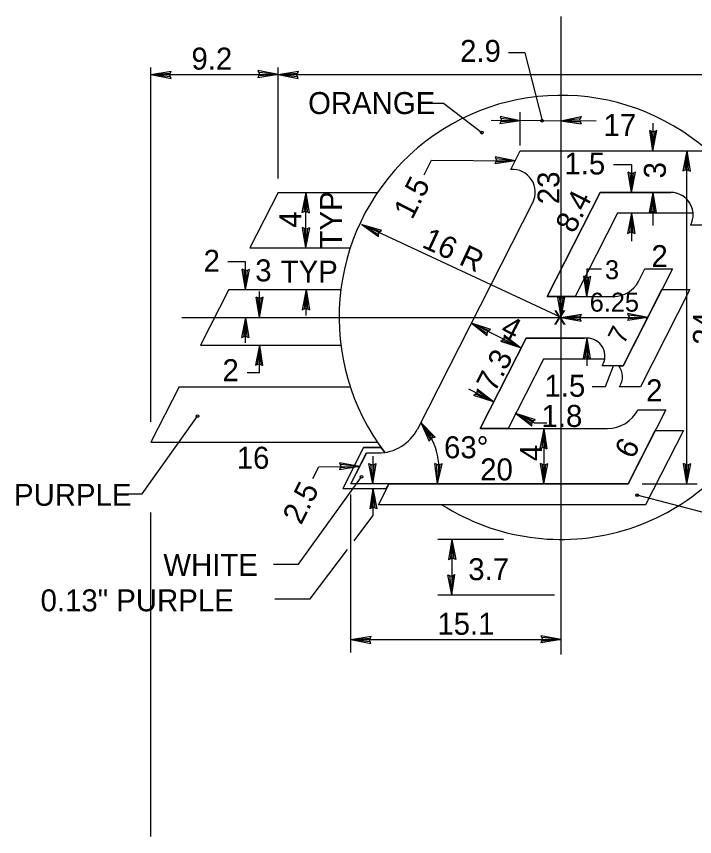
# Model space of a CAD drawing. Extents: x 10268197 to 10268739, y 2141503 to 2142677.
# Drawn here: x 10268594.88 to 10268620.18, y 2142394.49 to 2142425.07 of the extents above; entities that cross this region are included whole.
import ezdxf

# ---------------------------------------------------------------- set-up
doc = ezdxf.new("R2010")
doc.units = 0
doc.layers.add('1', color=7, linetype='Continuous')
doc.layers.add('Default', color=7, linetype='Continuous')

msp = doc.modelspace()

# ---------------------------------------------------------------- linework, layer by layer
at = {"layer": '1'}
for p, q in [((10268615.194, 2142401.275), (10268615.194, 2142425.067)), ((10268613.842, 2142423.705), (10268613.233, 2142423.709)), ((10268613.842, 2142423.705), (10268614.486, 2142421.186)), ((10268599.897, 2142409.949), (10268599.897, 2142423.161)), ((10268604.638, 2142419.022), (10268604.638, 2142423.161)), ((10268599.897, 2142422.903), (10268627.032, 2142422.903)), ((10268609.875, 2142421.837), (10268610.811, 2142421.837)), ((10268610.811, 2142421.837), (10268612.239, 2142420.735)), ((10268613.674, 2142420.255), (10268613.674, 2142421.491)), ((10268616.504, 2142421.161), (10268612.583, 2142421.189)), ((10268618.623, 2142421.091), (10268618.623, 2142420.056)), ((10268619.885, 2142407.638), (10268619.885, 2142420.056)), ((10268610.085, 2142419.159), (10268610.366, 2142419.708)), ((10268610.366, 2142419.708), (10268613.483, 2142419.68)), ((10268617.823, 2142419.539), (10268617.147, 2142419.539)), ((10268617.823, 2142419.539), (10268617.823, 2142418.504)), ((10268605.673, 2142416.434), (10268605.673, 2142418.504)), ((10268614.678, 2142414.624), (10268616.655, 2142418.504)), ((10268616.655, 2142418.504), (10268619.293, 2142418.504)), ((10268618.623, 2142418.504), (10268618.623, 2142417.274)), ((10268617.305, 2142417.728), (10268615.723, 2142414.624)), ((10268620.12, 2142417.728), (10268617.305, 2142417.728)), ((10268617.823, 2142417.728), (10268617.823, 2142416.693)), ((10268615.194, 2142413.847), (10268607.764, 2142417.312)), ((10268603.421, 2142415.917), (10268602.766, 2142415.921)), ((10268603.421, 2142414.882), (10268603.421, 2142415.917)), ((10268616.158, 2142415.659), (10268616.158, 2142414.624)), ((10268616.158, 2142415.659), (10268616.708, 2142415.659)), ((10268605.685, 2142413.912), (10268605.685, 2142414.882)), ((10268617.505, 2142412.037), (10268618.955, 2142414.882)), ((10268620, 2142414.882), (10268618.154, 2142411.26)), ((10268618.955, 2142414.882), (10268620, 2142414.882)), ((10268603.939, 2142413.847), (10268603.939, 2142414.812)), ((10268615.723, 2142414.624), (10268614.678, 2142414.624)), ((10268601.046, 2142413.847), (10268618.427, 2142413.847)), ((10268603.421, 2142412.902), (10268603.421, 2142413.847)), ((10268613.681, 2142412.706), (10268611.836, 2142413.646)), ((10268612.174, 2142409.708), (10268613.888, 2142413.071)), ((10268613.888, 2142413.071), (10268616.061, 2142413.064)), ((10268616.158, 2142413.071), (10268616.158, 2142412.037)), ((10268603.939, 2142411.778), (10268603.939, 2142412.812)), ((10268614.537, 2142412.293), (10268613.219, 2142409.708)), ((10268616.821, 2142412.286), (10268614.537, 2142412.293)), ((10268616.851, 2142411.274), (10268617.15, 2142412.037)), ((10268617.342, 2142412.037), (10268617.505, 2142412.037)), ((10268603.939, 2142411.778), (10268603.481, 2142411.782)), ((10268616.355, 2142411.274), (10268616.851, 2142411.274)), ((10268618.154, 2142411.26), (10268617.379, 2142411.26)), ((10268612.67, 2142410.696), (10268611.749, 2142411.166)), ((10268599.572, 2142407.264), (10268601.628, 2142410.163)), ((10268614.192, 2142409.92), (10268613.5, 2142410.272)), ((10268613.219, 2142409.708), (10268612.174, 2142409.708)), ((10268614.192, 2142409.92), (10268614.668, 2142409.92)), ((10268614.548, 2142409.708), (10268614.548, 2142407.638)), ((10268617.696, 2142407.638), (10268618.71, 2142409.629)), ((10268619.756, 2142409.629), (10268618.346, 2142406.862)), ((10268618.71, 2142409.629), (10268619.756, 2142409.629)), ((10268608.175, 2142408.675), (10268608.175, 2142407.646)), ((10268605.939, 2142407.845), (10268606.159, 2142408.277)), ((10268606.159, 2142408.277), (10268607.68, 2142408.29)), ((10268605.398, 2142404.639), (10268607.746, 2142407.901)), ((10268608.382, 2142406.862), (10268608.778, 2142407.638)), ((10268608.778, 2142407.638), (10268617.696, 2142407.638)), ((10268618.214, 2142407.638), (10268620.273, 2142407.638)), ((10268598.854, 2142407.264), (10268599.572, 2142407.264)), ((10268607.348, 2142401.35), (10268607.348, 2142407.242)), ((10268608.175, 2142407.462), (10268608.175, 2142406.442)), ((10268620.693, 2142406.521), (10268618.036, 2142407.216)), ((10268618.346, 2142406.862), (10268608.382, 2142406.862)), ((10268599.881, 2142406.567), (10268599.881, 2142394.488)), ((10268607.473, 2142405.515), (10268608.175, 2142406.442)), ((10268613.051, 2142405.568), (10268610.6, 2142405.568)), ((10268611.117, 2142405.568), (10268611.117, 2142403.499)), ((10268605.831, 2142403.347), (10268607.225, 2142405.188)), ((10268604.461, 2142404.639), (10268605.398, 2142404.639)), ((10268604.517, 2142403.347), (10268605.831, 2142403.347)), ((10268610.6, 2142403.499), (10268614.951, 2142403.499)), ((10268607.348, 2142401.837), (10268615.194, 2142401.837))]:
    msp.add_line(p, q, dxfattribs=at)
msp.add_lwpolyline([(10268608.487, 2142408.993), (10268607.826, 2142408.993), (10268607.048, 2142407.462), (10268608.671, 2142407.462), (10268608.778, 2142407.638), (10268607.348, 2142407.638), (10268607.95, 2142408.79), (10268608.375, 2142408.79), (10268608.623, 2142408.81)], close=True, dxfattribs=at)
for centre in [(10268614.483, 2142421.18), (10268612.238, 2142420.734), (10268601.628, 2142410.162), (10268607.746, 2142407.901), (10268618.036, 2142407.215)]:
    msp.add_circle(centre, 0.0517, dxfattribs=at)
for centre, radius, start, end in [((10268619.293, 2142417.675), 0.828, 3.5833, 90), ((10268616.158, 2142412.398), 0.673, 350.3502, 98.3344), ((10268616.812, 2142411.622), 0.673, 327.421, 37.9799), ((10268608.053, 2142408.174), 2.587, 348.03, 42.5026)]:
    msp.add_arc(centre, radius, start, end, dxfattribs=at)
at = {"layer": 'Default'}
for p, q in [((10268599.897, 2142422.903), (10268600.654, 2142423.022)), ((10268599.897, 2142422.903), (10268600.622, 2142422.953)), ((10268599.897, 2142422.903), (10268600.649, 2142422.756)), ((10268599.897, 2142422.903), (10268600.62, 2142422.826)), ((10268600.593, 2142422.89), (10268600.654, 2142423.022)), ((10268600.649, 2142422.756), (10268600.593, 2142422.89)), ((10268603.942, 2142422.914), (10268603.882, 2142422.782)), ((10268604.638, 2142422.903), (10268603.882, 2142422.782)), ((10268604.638, 2142422.903), (10268603.886, 2142423.048)), ((10268603.886, 2142423.048), (10268603.942, 2142422.914)), ((10268604.638, 2142422.903), (10268603.914, 2142422.852)), ((10268604.638, 2142422.903), (10268603.915, 2142422.978)), ((10268604.638, 2142422.903), (10268605.395, 2142423.022)), ((10268604.638, 2142422.903), (10268605.363, 2142422.953)), ((10268604.638, 2142422.903), (10268605.39, 2142422.756)), ((10268604.638, 2142422.903), (10268605.361, 2142422.826)), ((10268605.334, 2142422.89), (10268605.395, 2142423.022)), ((10268605.39, 2142422.756), (10268605.334, 2142422.89)), ((10268613.672, 2142421.178), (10268612.922, 2142421.331)), ((10268612.922, 2142421.331), (10268612.976, 2142421.197)), ((10268615.19, 2142421.178), (10268615.94, 2142421.331)), ((10268615.94, 2142421.331), (10268615.886, 2142421.197)), ((10268612.976, 2142421.197), (10268612.915, 2142421.065)), ((10268613.672, 2142421.178), (10268612.915, 2142421.065)), ((10268613.672, 2142421.178), (10268612.947, 2142421.134)), ((10268613.672, 2142421.178), (10268612.95, 2142421.26)), ((10268615.19, 2142421.178), (10268615.912, 2142421.26)), ((10268615.19, 2142421.178), (10268615.947, 2142421.065)), ((10268615.19, 2142421.178), (10268615.915, 2142421.134)), ((10268615.886, 2142421.197), (10268615.947, 2142421.065)), ((10268618.623, 2142420.056), (10268618.503, 2142420.813)), ((10268618.634, 2142420.753), (10268618.503, 2142420.813)), ((10268618.623, 2142420.056), (10268618.572, 2142420.781)), ((10268618.623, 2142420.056), (10268618.769, 2142420.808)), ((10268618.623, 2142420.056), (10268618.698, 2142420.779)), ((10268618.769, 2142420.808), (10268618.634, 2142420.753)), ((10268613.483, 2142419.68), (10268612.733, 2142419.832)), ((10268612.733, 2142419.832), (10268612.786, 2142419.698)), ((10268613.321, 2142419.362), (10268613.674, 2142420.056)), ((10268613.674, 2142420.056), (10268622.471, 2142420.056)), ((10268619.885, 2142420.056), (10268619.739, 2142419.305)), ((10268619.885, 2142420.056), (10268619.81, 2142419.334)), ((10268619.885, 2142420.056), (10268620.005, 2142419.3)), ((10268619.885, 2142420.056), (10268619.935, 2142419.332)), ((10268612.786, 2142419.698), (10268612.725, 2142419.567)), ((10268613.483, 2142419.68), (10268612.725, 2142419.567)), ((10268613.483, 2142419.68), (10268612.758, 2142419.636)), ((10268613.483, 2142419.68), (10268612.761, 2142419.762)), ((10268617.823, 2142418.504), (10268617.702, 2142419.261)), ((10268617.834, 2142419.201), (10268617.702, 2142419.261)), ((10268617.823, 2142418.504), (10268617.772, 2142419.229)), ((10268617.823, 2142418.504), (10268617.969, 2142419.256)), ((10268617.823, 2142418.504), (10268617.898, 2142419.227)), ((10268617.969, 2142419.256), (10268617.834, 2142419.201)), ((10268619.739, 2142419.305), (10268619.872, 2142419.36)), ((10268619.872, 2142419.36), (10268620.005, 2142419.3)), ((10268604.638, 2142418.504), (10268603.585, 2142416.434)), ((10268604.638, 2142418.504), (10268608.349, 2142418.504)), ((10268605.673, 2142418.504), (10268605.527, 2142417.752)), ((10268605.673, 2142418.504), (10268605.597, 2142417.782)), ((10268605.673, 2142418.504), (10268605.793, 2142417.748)), ((10268605.673, 2142418.504), (10268605.724, 2142417.78)), ((10268616.655, 2142418.504), (10268614.678, 2142414.624)), ((10268614.678, 2142414.624), (10268616.655, 2142418.504)), ((10268619.293, 2142418.504), (10268616.655, 2142418.504)), ((10268616.655, 2142418.504), (10268619.293, 2142418.504)), ((10268618.623, 2142418.504), (10268618.476, 2142417.752)), ((10268618.623, 2142418.504), (10268618.547, 2142417.782)), ((10268618.623, 2142418.504), (10268618.743, 2142417.748)), ((10268618.623, 2142418.504), (10268618.673, 2142417.78)), ((10268609.845, 2142409.694), (10268614.139, 2142418.123)), ((10268605.527, 2142417.752), (10268605.661, 2142417.808)), ((10268605.661, 2142417.808), (10268605.793, 2142417.748)), ((10268617.305, 2142417.728), (10268615.723, 2142414.624)), ((10268620.12, 2142417.728), (10268617.305, 2142417.728)), ((10268617.823, 2142417.728), (10268617.677, 2142416.977)), ((10268617.823, 2142417.728), (10268617.747, 2142417.005)), ((10268617.823, 2142417.728), (10268617.943, 2142416.971)), ((10268617.823, 2142417.728), (10268617.874, 2142417.004)), ((10268618.476, 2142417.752), (10268618.611, 2142417.808)), ((10268618.611, 2142417.808), (10268618.743, 2142417.748)), ((10268605.673, 2142416.434), (10268605.553, 2142417.191)), ((10268605.685, 2142417.131), (10268605.553, 2142417.191)), ((10268605.673, 2142416.434), (10268605.622, 2142417.159)), ((10268605.673, 2142416.434), (10268605.819, 2142417.186)), ((10268605.673, 2142416.434), (10268605.748, 2142417.157)), ((10268605.819, 2142417.186), (10268605.685, 2142417.131)), ((10268607.764, 2142417.312), (10268608.5, 2142417.101)), ((10268607.764, 2142417.312), (10268608.384, 2142416.862)), ((10268607.764, 2142417.312), (10268608.387, 2142416.938)), ((10268607.764, 2142417.312), (10268608.442, 2142417.052)), ((10268608.39, 2142417.007), (10268608.5, 2142417.101)), ((10268617.677, 2142416.977), (10268617.811, 2142417.031)), ((10268617.811, 2142417.031), (10268617.943, 2142416.971)), ((10268621.062, 2142417.29), (10268620.026, 2142417.29)), ((10268608.384, 2142416.862), (10268608.39, 2142417.007)), ((10268603.585, 2142416.434), (10268607.329, 2142416.434)), ((10268603.421, 2142414.882), (10268603.301, 2142415.639)), ((10268603.433, 2142415.579), (10268603.301, 2142415.639)), ((10268603.421, 2142414.882), (10268603.371, 2142415.607)), ((10268603.421, 2142414.882), (10268603.568, 2142415.634)), ((10268603.421, 2142414.882), (10268603.497, 2142415.605)), ((10268603.568, 2142415.634), (10268603.433, 2142415.579)), ((10268619.35, 2142415.659), (10268617.505, 2142412.037)), ((10268618.076, 2142415.188), (10268618.315, 2142415.659)), ((10268618.315, 2142415.659), (10268619.35, 2142415.659)), ((10268616.158, 2142414.624), (10268616.039, 2142415.38)), ((10268616.171, 2142415.32), (10268616.039, 2142415.38)), ((10268616.158, 2142414.624), (10268616.108, 2142415.348)), ((10268616.158, 2142414.624), (10268616.304, 2142415.375)), ((10268616.158, 2142414.624), (10268616.234, 2142415.346)), ((10268616.304, 2142415.375), (10268616.171, 2142415.32)), ((10268602.795, 2142414.882), (10268601.741, 2142412.812)), ((10268602.795, 2142414.882), (10268606.979, 2142414.882)), ((10268605.685, 2142414.882), (10268605.539, 2142414.13)), ((10268605.685, 2142414.882), (10268605.61, 2142414.16)), ((10268605.685, 2142414.882), (10268605.805, 2142414.126)), ((10268605.685, 2142414.882), (10268605.736, 2142414.158)), ((10268617.505, 2142412.037), (10268618.955, 2142414.882)), ((10268620, 2142414.882), (10268618.154, 2142411.26)), ((10268618.955, 2142414.882), (10268620, 2142414.882)), ((10268603.939, 2142413.847), (10268603.819, 2142414.604)), ((10268603.951, 2142414.544), (10268603.819, 2142414.604)), ((10268603.939, 2142413.847), (10268603.888, 2142414.572)), ((10268603.939, 2142413.847), (10268604.085, 2142414.599)), ((10268604.085, 2142414.599), (10268603.951, 2142414.544)), ((10268614.678, 2142414.624), (10268617.154, 2142414.624)), ((10268615.723, 2142414.624), (10268614.678, 2142414.624)), ((10268615.194, 2142413.847), (10268615.073, 2142414.604)), ((10268615.205, 2142414.544), (10268615.073, 2142414.604)), ((10268615.194, 2142413.847), (10268615.143, 2142414.572)), ((10268615.194, 2142413.847), (10268615.34, 2142414.599)), ((10268615.34, 2142414.599), (10268615.205, 2142414.544)), ((10268603.939, 2142413.847), (10268604.015, 2142414.57)), ((10268615.194, 2142413.847), (10268615.269, 2142414.57)), ((10268605.539, 2142414.13), (10268605.673, 2142414.186)), ((10268605.673, 2142414.186), (10268605.805, 2142414.126)), ((10268615.194, 2142413.847), (10268615.95, 2142413.967)), ((10268615.89, 2142413.835), (10268615.95, 2142413.967)), ((10268618.427, 2142413.847), (10268617.676, 2142413.993)), ((10268617.676, 2142413.993), (10268617.731, 2142413.859)), ((10268603.421, 2142413.847), (10268603.275, 2142413.096)), ((10268603.421, 2142413.847), (10268603.346, 2142413.125)), ((10268603.421, 2142413.847), (10268603.542, 2142413.091)), ((10268603.421, 2142413.847), (10268603.472, 2142413.123)), ((10268615.194, 2142413.847), (10268615.918, 2142413.898)), ((10268615.194, 2142413.847), (10268615.945, 2142413.701)), ((10268615.194, 2142413.847), (10268615.916, 2142413.772)), ((10268615.945, 2142413.701), (10268615.89, 2142413.835)), ((10268617.731, 2142413.859), (10268617.671, 2142413.727)), ((10268618.427, 2142413.847), (10268617.671, 2142413.727)), ((10268618.427, 2142413.847), (10268617.703, 2142413.796)), ((10268618.427, 2142413.847), (10268617.705, 2142413.923)), ((10268611.836, 2142413.646), (10268612.565, 2142413.41)), ((10268611.836, 2142413.646), (10268612.44, 2142413.175)), ((10268611.836, 2142413.646), (10268612.446, 2142413.251)), ((10268611.836, 2142413.646), (10268612.505, 2142413.362)), ((10268612.452, 2142413.32), (10268612.565, 2142413.41)), ((10268603.275, 2142413.096), (10268603.41, 2142413.151)), ((10268603.41, 2142413.151), (10268603.542, 2142413.091)), ((10268613.888, 2142413.071), (10268612.174, 2142409.708)), ((10268612.174, 2142409.708), (10268613.888, 2142413.071)), ((10268612.44, 2142413.175), (10268612.452, 2142413.32)), ((10268613.077, 2142413.178), (10268613.065, 2142413.033)), ((10268613.681, 2142412.706), (10268613.071, 2142413.102)), ((10268613.681, 2142412.706), (10268613.077, 2142413.178)), ((10268616.158, 2142413.071), (10268613.888, 2142413.071)), ((10268613.888, 2142413.071), (10268616.061, 2142413.064)), ((10268616.158, 2142413.071), (10268616.013, 2142412.32)), ((10268616.158, 2142413.071), (10268616.083, 2142412.348)), ((10268616.158, 2142413.071), (10268616.279, 2142412.314)), ((10268616.158, 2142413.071), (10268616.209, 2142412.347)), ((10268601.741, 2142412.812), (10268606.979, 2142412.812)), ((10268603.939, 2142412.812), (10268603.793, 2142412.061)), ((10268603.939, 2142412.812), (10268603.863, 2142412.09)), ((10268603.939, 2142412.812), (10268604.059, 2142412.056)), ((10268603.939, 2142412.812), (10268603.989, 2142412.088)), ((10268613.065, 2142413.033), (10268612.952, 2142412.942)), ((10268613.681, 2142412.706), (10268612.952, 2142412.942)), ((10268613.681, 2142412.706), (10268613.012, 2142412.99)), ((10268614.537, 2142412.293), (10268613.219, 2142409.708)), ((10268616.821, 2142412.286), (10268614.537, 2142412.293)), ((10268616.013, 2142412.32), (10268616.147, 2142412.374)), ((10268616.147, 2142412.374), (10268616.279, 2142412.314)), ((10268603.793, 2142412.061), (10268603.927, 2142412.116)), ((10268603.927, 2142412.116), (10268604.059, 2142412.056)), ((10268617.505, 2142412.037), (10268616.726, 2142412.037)), ((10268617.342, 2142412.037), (10268617.505, 2142412.037)), ((10268600.951, 2142411.26), (10268599.897, 2142409.19)), ((10268600.951, 2142411.26), (10268607.329, 2142411.26)), ((10268618.154, 2142411.26), (10268617.379, 2142411.26)), ((10268612.055, 2142411.023), (10268611.942, 2142410.933)), ((10268612.67, 2142410.696), (10268611.942, 2142410.933)), ((10268612.67, 2142410.696), (10268612.002, 2142410.98)), ((10268612.067, 2142411.167), (10268612.055, 2142411.023)), ((10268612.67, 2142410.696), (10268612.061, 2142411.091)), ((10268612.67, 2142410.696), (10268612.067, 2142411.167)), ((10268619.106, 2142410.404), (10268617.696, 2142407.638)), ((10268618.07, 2142410.404), (10268619.106, 2142410.404)), ((10268613.5, 2142410.272), (10268614.229, 2142410.036)), ((10268613.5, 2142410.272), (10268614.104, 2142409.801)), ((10268613.5, 2142410.272), (10268614.11, 2142409.877)), ((10268613.5, 2142410.272), (10268614.169, 2142409.989)), ((10268614.115, 2142409.946), (10268614.229, 2142410.036)), ((10268609.96, 2142409.923), (10268610.497, 2142409.377)), ((10268609.96, 2142409.923), (10268610.279, 2142409.225)), ((10268609.96, 2142409.923), (10268610.318, 2142409.291)), ((10268609.96, 2142409.923), (10268610.423, 2142409.362)), ((10268612.174, 2142409.708), (10268616.923, 2142409.708)), ((10268613.219, 2142409.708), (10268612.174, 2142409.708)), ((10268614.104, 2142409.801), (10268614.115, 2142409.946)), ((10268614.548, 2142409.708), (10268614.402, 2142408.956)), ((10268614.548, 2142409.708), (10268614.472, 2142408.985)), ((10268614.548, 2142409.708), (10268614.668, 2142408.951)), ((10268614.548, 2142409.708), (10268614.598, 2142408.983)), ((10268610.355, 2142409.349), (10268610.497, 2142409.377)), ((10268617.696, 2142407.638), (10268618.71, 2142409.629)), ((10268619.756, 2142409.629), (10268618.346, 2142406.862)), ((10268618.71, 2142409.629), (10268619.756, 2142409.629)), ((10268599.897, 2142409.19), (10268608.349, 2142409.19)), ((10268610.279, 2142409.225), (10268610.355, 2142409.349)), ((10268607.826, 2142408.993), (10268607.048, 2142407.462)), ((10268607.348, 2142407.638), (10268607.935, 2142408.79)), ((10268607.826, 2142408.993), (10268608.487, 2142408.993)), ((10268607.935, 2142408.79), (10268608.369, 2142408.79)), ((10268614.402, 2142408.956), (10268614.536, 2142409.011)), ((10268614.536, 2142409.011), (10268614.668, 2142408.951)), ((10268606.983, 2142408.295), (10268606.924, 2142408.163)), ((10268607.68, 2142408.29), (10268606.924, 2142408.163)), ((10268607.68, 2142408.29), (10268606.926, 2142408.429)), ((10268606.926, 2142408.429), (10268606.983, 2142408.295)), ((10268607.68, 2142408.29), (10268606.956, 2142408.359)), ((10268607.68, 2142408.29), (10268606.956, 2142408.233)), ((10268608.175, 2142407.646), (10268608.029, 2142408.398)), ((10268608.029, 2142408.398), (10268608.163, 2142408.342)), ((10268608.175, 2142407.646), (10268608.1, 2142408.369)), ((10268608.163, 2142408.342), (10268608.295, 2142408.402)), ((10268608.175, 2142407.646), (10268608.295, 2142408.402)), ((10268608.175, 2142407.646), (10268608.226, 2142408.37)), ((10268610.584, 2142407.638), (10268610.49, 2142408.398)), ((10268610.62, 2142408.333), (10268610.49, 2142408.398)), ((10268610.584, 2142407.638), (10268610.559, 2142408.364)), ((10268610.584, 2142407.638), (10268610.756, 2142408.384)), ((10268610.584, 2142407.638), (10268610.684, 2142408.358)), ((10268610.756, 2142408.384), (10268610.62, 2142408.333)), ((10268614.548, 2142407.638), (10268614.428, 2142408.395)), ((10268614.56, 2142408.335), (10268614.428, 2142408.395)), ((10268614.548, 2142407.638), (10268614.497, 2142408.362)), ((10268614.548, 2142407.638), (10268614.694, 2142408.39)), ((10268614.548, 2142407.638), (10268614.624, 2142408.361)), ((10268614.694, 2142408.39), (10268614.56, 2142408.335)), ((10268619.885, 2142407.638), (10268619.765, 2142408.395)), ((10268619.897, 2142408.335), (10268619.765, 2142408.395)), ((10268619.885, 2142407.638), (10268619.834, 2142408.362)), ((10268619.885, 2142407.638), (10268620.03, 2142408.39)), ((10268619.885, 2142407.638), (10268619.96, 2142408.361)), ((10268620.03, 2142408.39), (10268619.897, 2142408.335)), ((10268617.696, 2142407.638), (10268607.348, 2142407.638)), ((10268608.382, 2142406.862), (10268608.778, 2142407.638)), ((10268608.778, 2142407.638), (10268617.696, 2142407.638)), ((10268607.048, 2142407.462), (10268608.671, 2142407.462)), ((10268608.175, 2142407.462), (10268608.055, 2142406.706)), ((10268608.175, 2142407.462), (10268608.125, 2142406.738)), ((10268608.175, 2142407.462), (10268608.321, 2142406.71)), ((10268608.175, 2142407.462), (10268608.251, 2142406.739)), ((10268608.187, 2142406.766), (10268608.055, 2142406.706)), ((10268608.321, 2142406.71), (10268608.187, 2142406.766)), ((10268618.346, 2142406.862), (10268608.382, 2142406.862)), ((10268611.117, 2142405.568), (10268610.997, 2142404.812)), ((10268611.117, 2142405.568), (10268611.066, 2142404.844)), ((10268611.117, 2142405.568), (10268611.263, 2142404.817)), ((10268611.117, 2142405.568), (10268611.192, 2142404.846)), ((10268611.128, 2142404.872), (10268610.997, 2142404.812)), ((10268611.263, 2142404.817), (10268611.128, 2142404.872)), ((10268611.117, 2142403.499), (10268610.971, 2142404.25)), ((10268610.971, 2142404.25), (10268611.105, 2142404.195)), ((10268611.117, 2142403.499), (10268611.041, 2142404.221)), ((10268611.105, 2142404.195), (10268611.237, 2142404.255)), ((10268611.117, 2142403.499), (10268611.237, 2142404.255)), ((10268611.117, 2142403.499), (10268611.168, 2142404.223)), ((10268607.348, 2142401.837), (10268608.104, 2142401.957)), ((10268607.348, 2142401.837), (10268608.072, 2142401.888)), ((10268607.348, 2142401.837), (10268608.099, 2142401.692)), ((10268607.348, 2142401.837), (10268608.07, 2142401.762)), ((10268608.044, 2142401.825), (10268608.104, 2142401.957)), ((10268608.099, 2142401.692), (10268608.044, 2142401.825)), ((10268614.497, 2142401.843), (10268614.439, 2142401.71)), ((10268615.194, 2142401.837), (10268614.439, 2142401.71)), ((10268615.194, 2142401.837), (10268614.44, 2142401.977)), ((10268614.44, 2142401.977), (10268614.497, 2142401.843)), ((10268615.194, 2142401.837), (10268614.47, 2142401.78)), ((10268615.194, 2142401.837), (10268614.471, 2142401.906))]:
    msp.add_line(p, q, dxfattribs=at)
for centre, radius, start, end in [((10268615.193, 2142413.846), 8.279, 48.5904, 217.4727), ((10268613.378, 2142418.51), 0.854, 332.9998, 93.8045), ((10268619.293, 2142417.675), 0.828, 332.2089, 90), ((10268619.293, 2142417.675), 0.828, 3.5833, 90), ((10268617.154, 2142415.657), 1.035, 270, 332.9883), ((10268616.158, 2142412.398), 0.673, 350.3502, 98.3344), ((10268616.158, 2142412.398), 0.673, 327.421, 90), ((10268616.812, 2142411.622), 0.673, 327.421, 37.9799), ((10268615.193, 2142413.846), 8.279, 237.5383, 335.047), ((10268616.922, 2142411.001), 1.294, 270, 332.5096), ((10268608.369, 2142410.446), 1.656, 270, 332.9991)]:
    msp.add_arc(centre, radius, start, end, dxfattribs=at)

# ---------------------------------------------------------------- texts
at = {"layer": '1'}
for s, height, p in [('2.9', 0.8187, (10268611.427, 2142423.372)), ('9.2', 0.8187, (10268601.407, 2142423.084)), ('ORANGE', 0.8187, (10268605.757, 2142421.427)), ('17', 0.8187, (10268616.78, 2142420.61)), ('1.5', 0.8187, (10268615.318, 2142419.173)), ('2', 0.819, (10268618.564, 2142415.72)), ('2', 0.819, (10268601.859, 2142415.546)), ('3', 0.819, (10268603.786, 2142415.189)), ('TYP', 0.8187, (10268604.736, 2142415.144)), ('3', 0.706, (10268616.831, 2142415.27)), ('6.25', 0.706, (10268616.263, 2142414.06)), ('x', 0.706, (10268614.912, 2142413.571)), ('2', 0.819, (10268602.563, 2142411.467)), ('1.5', 0.8187, (10268614.575, 2142410.887)), ('2', 0.819, (10268618.366, 2142410.717)), ('1.8', 0.8187, (10268614.465, 2142409.761)), ('63°', 0.8187, (10268610.829, 2142408.593)), ('16', 0.8187, (10268603.095, 2142408.204)), ('20', 0.8187, (10268612.177, 2142407.769)), ('PURPLE', 0.8187, (10268594.787, 2142406.821)), ('WHITE', 0.8187, (10268600.358, 2142404.209)), ('3.7', 0.8187, (10268611.732, 2142404.049)), ('0.13" PURPLE', 0.81867, (10268595.779, 2142402.887)), ('15.1', 0.8187, (10268610.58, 2142402.012))]:
    msp.add_text(s, height=height, dxfattribs=at).set_placement(p)
for s, height, rotation, p in [('3', 0.819, 90, (10268619.103, 2142419.026)), ('23', 0.8187, 90, (10268615.133, 2142418.066)), ('1.5', 0.8187, 63, (10268609.639, 2142417.459)), ('TYP', 0.8187, 90, (10268607.021, 2142416.416)), ('8.4', 0.8187, 63, (10268615.673, 2142416.94)), ('4', 0.819, 90, (10268605.503, 2142417.188)), ('16 R', 0.8187, 334.9991, (10268609.963, 2142416.482)), ('24', 0.8187, 90, (10268620.934, 2142412.827)), ('4', 0.819, 332.9866, (10268612.885, 2142413.225)), ('7', 0.706, 63, (10268617.533, 2142412.806)), ('7.3', 0.8187, 63, (10268612.725, 2142411.019)), ('6', 0.819, 63, (10268617.88, 2142408.526)), ('4', 0.819, 90, (10268614.485, 2142408.489)), ('2.5', 0.8187, 63, (10268605.496, 2142406.078))]:
    msp.add_text(s, height=height, rotation=rotation, dxfattribs=at).set_placement(p)

doc.saveas('drawing.dxf')
